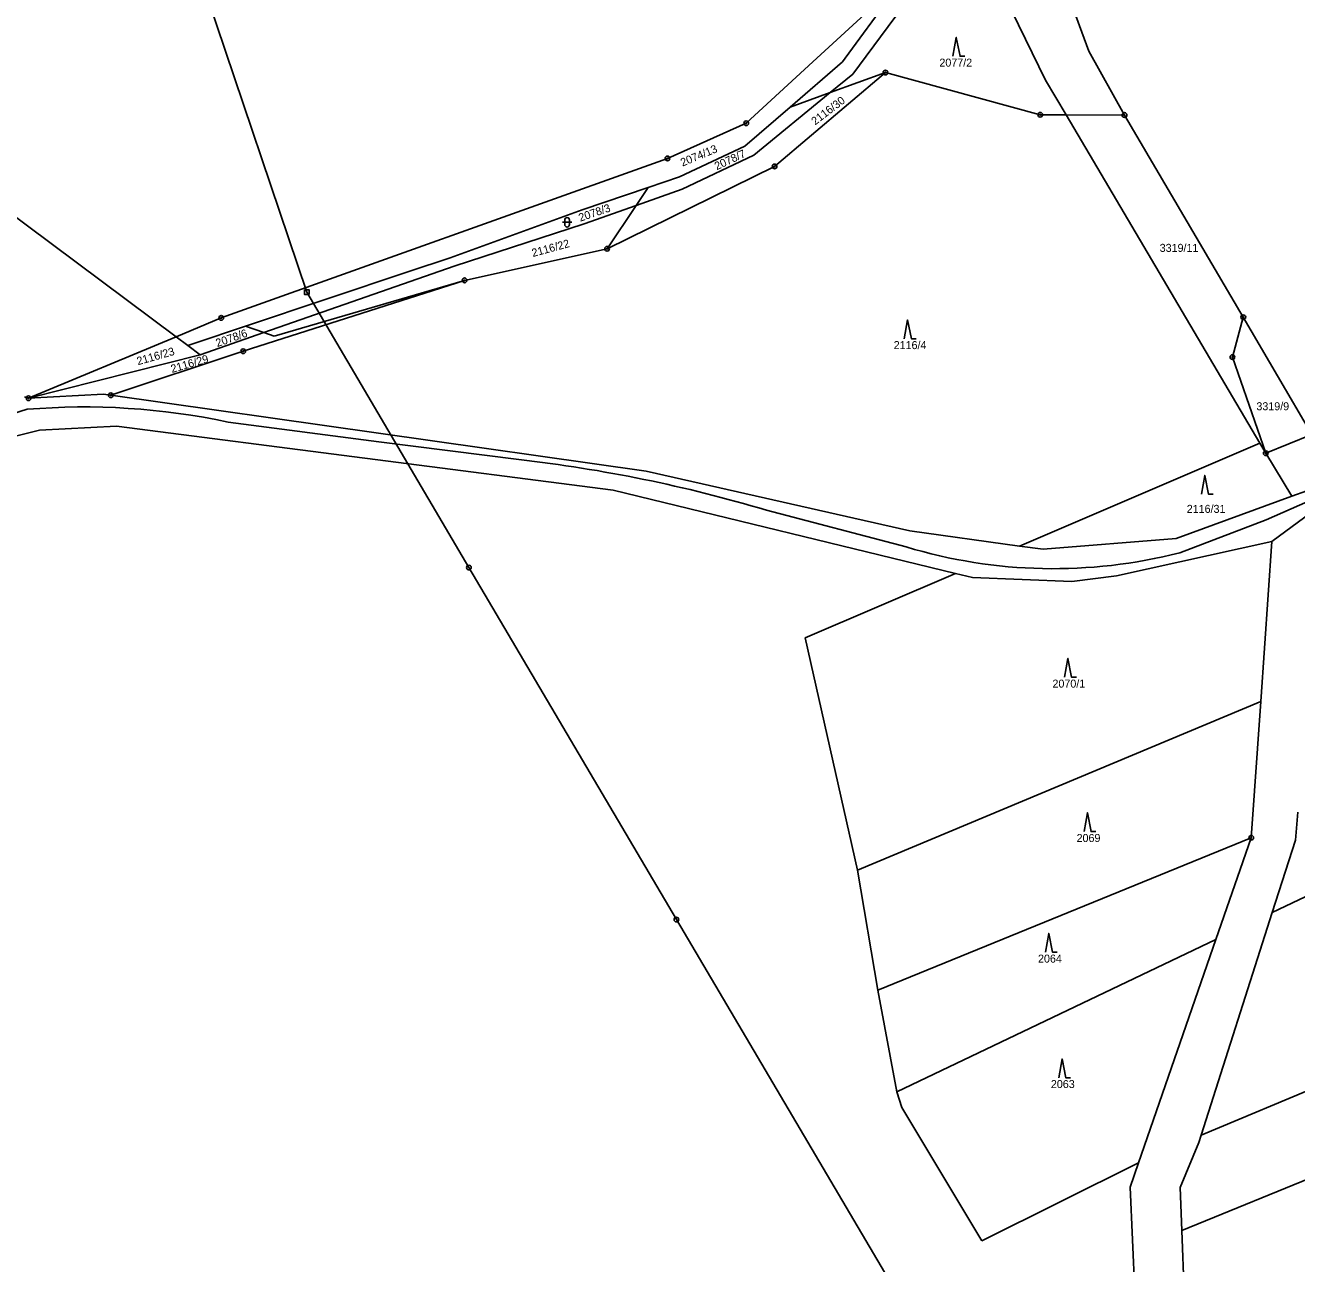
# Model space of a CAD drawing. Extents: x -763205 to -760228, y -1155311 to -1152844.
# Drawn here: x -762007.3 to -761737.4, y -1154027.2 to -1153764.2 of the extents above; entities that cross this region are included whole.
import ezdxf

# ---------------------------------------------------------------- set-up
doc = ezdxf.new("R2010")
doc.units = 0
for name, color, linetype in [('Vrstva 1', 7, 'Continuous'), ('Vrstva 10', 7, 'Continuous'), ('Vrstva 12', 7, 'Continuous'), ('Vrstva 18', 7, 'Continuous'), ('Vrstva 24', 7, 'Continuous'), ('Vrstva 25', 7, 'Continuous'), ('Vrstva 26', 7, 'Continuous'), ('Vrstva 6', 7, 'Continuous')]:
    doc.layers.add(name, color=color, linetype=linetype)

msp = doc.modelspace()

# ---------------------------------------------------------------- linework, layer by layer
at = {"layer": 'Vrstva 1'}
for p, q in [((-761799.26, -1153720.95), (-761781.52, -1153769.67)), ((-761833.21, -1153771.19), (-761808.52, -1153737.26)), ((-761828.77, -1153770.72), (-761807.33, -1153741.77)), ((-761807.33, -1153741.77), (-761794.91, -1153767.13)), ((-761840.07, -1153771.94), (-761827.38, -1153760.26)), ((-761794.91, -1153767.13), (-761790.66, -1153775.82)), ((-761781.52, -1153769.67), (-761773.92, -1153783.25)), ((-761854.25, -1153785), (-761840.07, -1153771.94)), ((-761844.91, -1153781.59), (-761833.77, -1153771.96)), ((-761833.77, -1153771.96), (-761833.21, -1153771.19)), ((-761831.63, -1153774.58), (-761828.77, -1153770.72)), ((-761848.22, -1153794.16), (-761824.7, -1153774.22)), ((-761836.41, -1153778.49), (-761831.63, -1153774.58)), ((-761824.7, -1153774.22), (-761791.82, -1153783.19)), ((-761790.66, -1153775.82), (-761786.3, -1153783.21)), ((-761852.65, -1153791.78), (-761836.41, -1153778.49)), ((-761854.52, -1153789.9), (-761844.91, -1153781.59)), ((-761791.82, -1153783.19), (-761786.3, -1153783.21)), ((-761786.3, -1153783.21), (-761773.92, -1153783.25)), ((-761786.3, -1153783.21), (-761745.17, -1153852.98)), ((-761773.92, -1153783.25), (-761748.69, -1153826.21)), ((-761870.97, -1153792.48), (-761854.25, -1153785)), ((-761868.43, -1153796.4), (-761854.52, -1153789.9)), ((-761965.72, -1153826.34), (-761870.97, -1153792.48)), ((-761883.78, -1153811.66), (-761848.22, -1153794.16)), ((-761867.83, -1153798.97), (-761852.65, -1153791.78)), ((-761875.1, -1153798.67), (-761868.43, -1153796.4)), ((-761889.06, -1153803.41), (-761875.1, -1153798.67)), ((-761877.63, -1153802.46), (-761867.83, -1153798.97)), ((-761888.65, -1153806.38), (-761877.63, -1153802.46)), ((-762012.18, -1153802.81), (-761975.33, -1153830.35)), ((-761917.14, -1153813.62), (-761889.06, -1153803.41)), ((-761916.23, -1153815.35), (-761888.65, -1153806.38)), ((-761914.05, -1153818.37), (-761883.78, -1153811.66)), ((-761956.67, -1153829.45), (-761916.23, -1153815.35)), ((-761925.86, -1153816.47), (-761917.14, -1153813.62)), ((-761961.06, -1153833.44), (-761914.05, -1153818.37)), ((-761960.57, -1153828.11), (-761925.86, -1153816.47)), ((-761975.33, -1153830.35), (-761965.72, -1153826.34)), ((-761751.01, -1153834.67), (-761748.69, -1153826.21)), ((-761748.69, -1153826.21), (-761734.13, -1153851.1)), ((-761971.55, -1153831.79), (-761960.57, -1153828.11)), ((-761970.22, -1153834.17), (-761956.67, -1153829.45)), ((-762006.64, -1153843.41), (-761975.33, -1153830.35)), ((-761975.33, -1153830.35), (-761972.83, -1153832.22)), ((-761972.83, -1153832.22), (-761971.55, -1153831.79)), ((-762006.64, -1153843.41), (-761970.22, -1153834.17)), ((-761989.19, -1153842.78), (-761961.06, -1153833.44)), ((-761972.83, -1153832.22), (-761970.22, -1153834.17)), ((-761751.01, -1153834.67), (-761743.92, -1153855.1)), ((-762006.64, -1153843.41), (-761990.7, -1153842.57)), ((-761990.7, -1153842.57), (-761989.19, -1153842.78)), ((-761989.19, -1153842.78), (-761875.47, -1153858.91)), ((-762007.47, -1153843.14), (-762006.64, -1153843.41)), ((-762034.45, -1153857.73), (-762004.33, -1153850.2)), ((-762004.33, -1153850.2), (-761987.96, -1153849.37)), ((-761987.96, -1153849.37), (-761882.52, -1153862.92)), ((-761745.17, -1153852.98), (-761743.92, -1153855.1)), ((-761743.92, -1153855.1), (-761734.13, -1153851.1)), ((-761743.92, -1153855.1), (-761738.36, -1153864.23)), ((-761875.47, -1153858.91), (-761819.49, -1153871.59)), ((-761882.52, -1153862.92), (-761809.82, -1153880.64)), ((-761762.94, -1153873.18), (-761738.36, -1153864.23)), ((-761738.36, -1153864.23), (-761732, -1153861.96)), ((-761742.64, -1153873.82), (-761731.6, -1153865.71)), ((-761819.49, -1153871.59), (-761796.21, -1153874.82)), ((-761796.21, -1153874.82), (-761791.22, -1153875.51)), ((-761791.22, -1153875.51), (-761762.94, -1153873.18)), ((-761775.61, -1153881.12), (-761742.64, -1153873.82)), ((-761745, -1153907.84), (-761742.64, -1153873.82)), ((-761809.82, -1153880.64), (-761806.18, -1153881.53)), ((-761806.18, -1153881.53), (-761785.1, -1153882.33)), ((-761785.1, -1153882.33), (-761775.61, -1153881.12)), ((-761747.01, -1153936.79), (-761745, -1153907.84)), ((-761737.63, -1153937.28), (-761737.13, -1153931.38)), ((-761754.5, -1153958.39), (-761747.01, -1153936.79)), ((-761742.54, -1153952.68), (-761737.63, -1153937.28)), ((-761757.64, -1153999.96), (-761742.54, -1153952.68)), ((-761770.95, -1154005.84), (-761754.5, -1153958.39)), ((-761762.1, -1154011.05), (-761758.15, -1154001.55)), ((-761758.15, -1154001.55), (-761757.64, -1153999.96)), ((-761772.74, -1154010.99), (-761770.95, -1154005.84)), ((-761772.74, -1154010.99), (-761770.15, -1154069.65)), ((-761762.1, -1154011.05), (-761761.76, -1154020.22)), ((-761761.76, -1154020.22), (-761760.68, -1154049.22))]:
    msp.add_line(p, q, dxfattribs=at)
at = {"layer": 'Vrstva 10'}
for p, q in [((-762045.35, -1153857.64), (-762006.96, -1153845.77)), ((-761932.29, -1153852.67), (-761964.23, -1153848.47)), ((-761902.53, -1153856.45), (-761932.29, -1153852.67)), ((-761731.48, -1153863.83), (-761743.84, -1153869.27)), ((-761849.97, -1153867.2), (-761820.28, -1153875)), ((-761743.84, -1153869.27), (-761762.19, -1153876.23))]:
    msp.add_line(p, q, dxfattribs=at)
for centre, radius, start, end in [((-761994.803, -1153992.845), 147.577, 78.04362, 94.72524), ((-761936.458, -1154156.2), 301.664, 73.33933, 83.54231), ((-761789.037, -1153771.806), 107.82, 253.15576, 284.41824)]:
    msp.add_arc(centre, radius, start, end, dxfattribs=at)
at = {"layer": 'Vrstva 12'}
for p, q in [((-761972.17, -1153747.84), (-761947.56, -1153820.86)), ((-761947.56, -1153820.86), (-761913.14, -1153879.39)), ((-761913.14, -1153879.39), (-761869.08, -1153954.17)), ((-761869.08, -1153954.17), (-761822.06, -1154033.87))]:
    msp.add_line(p, q, dxfattribs=at)
at = {"layer": 'Vrstva 24'}
for centre, radius in [((-761824.7, -1153774.22), 0.5), ((-761824.7, -1153774.22), 0.1), ((-761791.82, -1153783.19), 0.5), ((-761791.82, -1153783.19), 0.1), ((-761773.92, -1153783.25), 0.5), ((-761773.92, -1153783.25), 0.1), ((-761854.25, -1153785), 0.5), ((-761854.25, -1153785), 0.1), ((-761870.97, -1153792.48), 0.5), ((-761870.97, -1153792.48), 0.1), ((-761848.22, -1153794.16), 0.5), ((-761848.22, -1153794.16), 0.1), ((-761883.78, -1153811.66), 0.5), ((-761883.78, -1153811.66), 0.1), ((-761914.05, -1153818.37), 0.5), ((-761914.05, -1153818.37), 0.1), ((-761965.72, -1153826.34), 0.5), ((-761965.72, -1153826.34), 0.1), ((-761748.69, -1153826.21), 0.5), ((-761748.69, -1153826.21), 0.1), ((-761961.06, -1153833.44), 0.5), ((-761961.06, -1153833.44), 0.1), ((-761751.01, -1153834.67), 0.5), ((-761751.01, -1153834.67), 0.1), ((-762006.64, -1153843.41), 0.5), ((-761989.19, -1153842.78), 0.5), ((-761989.19, -1153842.78), 0.1), ((-762006.64, -1153843.41), 0.1), ((-761743.92, -1153855.1), 0.5), ((-761743.92, -1153855.1), 0.1), ((-761747.01, -1153936.79), 0.5), ((-761747.01, -1153936.79), 0.1)]:
    msp.add_circle(centre, radius, dxfattribs=at)
at = {"layer": 'Vrstva 25'}
for p, q in [((-761893.28, -1153806.04), (-761891.28, -1153806.04)), ((-761892.78, -1153806.54), (-761892.78, -1153805.54)), ((-761891.78, -1153805.54), (-761891.78, -1153806.54))]:
    msp.add_line(p, q, dxfattribs=at)
for points in [[(-761810.34, -1153770.77), (-761809.64, -1153766.77), (-761808.84, -1153770.77), (-761807.84, -1153770.77)], [(-761820.68, -1153830.78), (-761819.98, -1153826.78), (-761819.18, -1153830.78), (-761818.18, -1153830.78)], [(-761757.57, -1153863.82), (-761756.87, -1153859.82), (-761756.07, -1153863.82), (-761755.07, -1153863.82)], [(-761786.64, -1153902.69), (-761785.94, -1153898.69), (-761785.14, -1153902.69), (-761784.14, -1153902.69)], [(-761782.51, -1153935.49), (-761781.81, -1153931.49), (-761781.01, -1153935.49), (-761780.01, -1153935.49)], [(-761790.7, -1153961.11), (-761790, -1153957.11), (-761789.2, -1153961.11), (-761788.2, -1153961.11)], [(-761787.89, -1153987.76), (-761787.19, -1153983.76), (-761786.39, -1153987.76), (-761785.39, -1153987.76)]]:
    msp.add_lwpolyline(points, dxfattribs=at)
for centre, start, end in [((-761892.28, -1153805.54), 0, 180), ((-761892.28, -1153806.54), 180, 0)]:
    msp.add_arc(centre, 0.5, start, end, dxfattribs=at)
at = {"layer": 'Vrstva 26'}
msp.add_lwpolyline([(-761948.06, -1153820.36), (-761947.06, -1153820.36), (-761947.06, -1153821.36), (-761948.06, -1153821.36)], close=True, dxfattribs=at)
for centre in [(-761913.14, -1153879.39), (-761869.08, -1153954.17)]:
    msp.add_circle(centre, 0.5, dxfattribs=at)
at = {"layer": 'Vrstva 6'}
for p, q in [((-761836.41, -1153778.49), (-761824.7, -1153774.22)), ((-761844.91, -1153781.59), (-761836.41, -1153778.49)), ((-761877.63, -1153802.46), (-761875.1, -1153798.67)), ((-761883.78, -1153811.66), (-761877.63, -1153802.46)), ((-761954.45, -1153830.21), (-761914.05, -1153818.37)), ((-761960.57, -1153828.11), (-761956.67, -1153829.45)), ((-761956.67, -1153829.45), (-761954.45, -1153830.21)), ((-761796.21, -1153874.82), (-761745.17, -1153852.98)), ((-761841.74, -1153894.3), (-761809.82, -1153880.64)), ((-761841.74, -1153894.3), (-761830.6, -1153943.69)), ((-761830.6, -1153943.69), (-761745, -1153907.84)), ((-761742.54, -1153952.68), (-761665.34, -1153915.8)), ((-761826.29, -1153969.15), (-761747.01, -1153936.79)), ((-761830.6, -1153943.69), (-761826.29, -1153969.15)), ((-761822.24, -1153990.74), (-761754.5, -1153958.39)), ((-761826.29, -1153969.15), (-761822.24, -1153990.74)), ((-761761.76, -1154020.22), (-761645.8, -1153972.85)), ((-761757.64, -1153999.96), (-761719.2, -1153983.85)), ((-761822.24, -1153990.74), (-761821.18, -1153994.09)), ((-761821.18, -1153994.09), (-761804.21, -1154022.4)), ((-761804.21, -1154022.4), (-761770.95, -1154005.84))]:
    msp.add_line(p, q, dxfattribs=at)

# ---------------------------------------------------------------- texts
at = {"layer": 'Vrstva 18'}
for s, p in [('2077/2', (-761813.223, -1153772.97)), ('3319/11', (-761766.443, -1153812.32)), ('2116/4', (-761822.933, -1153832.98)), ('3319/9', (-761745.913, -1153845.97)), ('2116/31', (-761760.703, -1153867.77)), ('2070/1', (-761789.213, -1153904.89)), ('2069', (-761784.093, -1153937.69)), ('2064', (-761792.283, -1153963.31)), ('2063', (-761789.553, -1153989.96))]:
    msp.add_text(s, height=1.7, dxfattribs=at).set_placement(p)
for s, rotation, p in [('2116/30', 37.29955, (-761839.621, -1153785.476)), ('2074/13', 22.63183, (-761867.781, -1153794.219)), ('2078/7', 24.98096, (-761860.505, -1153794.99)), ('2078/3', 18.85031, (-761889.495, -1153805.923)), ('2116/22', 15.18338, (-761899.541, -1153813.418)), ('2078/6', 19.25138, (-761966.556, -1153832.562)), ('2116/23', 15.75634, (-761983.402, -1153836.406)), ('2116/29', 16.21471, (-761976.172, -1153838.054))]:
    msp.add_text(s, height=1.7, rotation=rotation, dxfattribs=at).set_placement(p)

doc.saveas('drawing.dxf')
